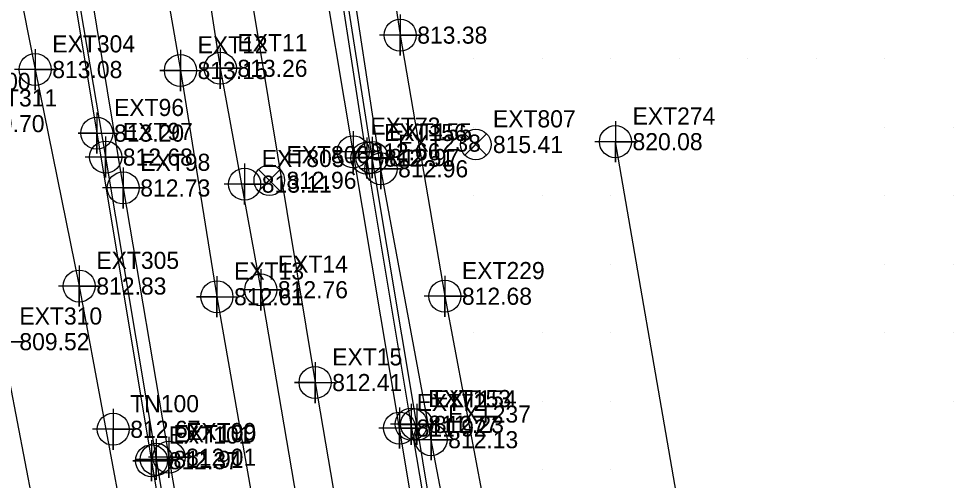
# Model space of a CAD drawing. Extents: x 1762120 to 1766775, y 709485 to 712965.
# Drawn here: x 1763773.6 to 1763910, y 712748.4 to 712815.9 of the extents above; entities that cross this region are included whole.
import ezdxf

# ---------------------------------------------------------------- set-up
doc = ezdxf.new("R2010")
doc.units = 0
for name, color, linetype in [('Default Symbol CELL', 7, 'Continuous'), ('Default Symbol Cogo Elevation', 7, 'Continuous'), ('Default Symbol Cogo Number', 7, 'Continuous'), ('Exist Building', 7, 'Continuous'), ('Exist Building Cogo Elevation', 7, 'Continuous'), ('Exist Building Cogo Number', 7, 'Continuous'), ('Exist Building Cogo Point CELL', 7, 'Continuous'), ('Exist DTM Breakline', 7, 'Continuous'), ('Exist DTM Breakline Cogo Elevation', 7, 'Continuous'), ('Exist DTM Breakline Cogo Number', 7, 'Continuous'), ('Exist DTM Breakline Cogo Point CELL', 7, 'Continuous'), ('Exist DTM Crownline', 7, 'Continuous'), ('Exist DTM Crownline Cogo Elevation', 7, 'Continuous'), ('Exist DTM Crownline Cogo Number', 7, 'Continuous'), ('Exist DTM Crownline Cogo Point CELL', 7, 'Continuous'), ('Exist DTM Drainline', 7, 'Continuous'), ('Exist DTM Drainline Cogo Elevation', 7, 'Continuous'), ('Exist DTM Drainline Cogo Number', 7, 'Continuous'), ('Exist DTM Drainline Cogo Point CELL', 7, 'Continuous'), ('Exist DTM QL2 LIDAR Elevation Point', 7, 'Continuous'), ('Exist Other Culture Fence Line Cogo Number', 7, 'Continuous'), ('Exist Roads Curbs', 7, 'Continuous'), ('Exist Roads Curbs Cogo Elevation', 7, 'Continuous'), ('Exist Roads Curbs Cogo Number', 7, 'Continuous'), ('Exist Roads Curbs Cogo Point CELL', 7, 'Continuous'), ('Exist Roads EOP', 7, 'Continuous'), ('Exist Roads EOP Cogo Elevation', 7, 'Continuous'), ('Exist Roads EOP Cogo Number', 7, 'Continuous'), ('Exist Roads EOP Cogo Point CELL', 7, 'Continuous'), ('Exist Roads EOP Other', 7, 'Continuous'), ('Exist Roads EOP Other Cogo Elevation', 7, 'Continuous'), ('Exist Roads EOP Other Cogo Number', 7, 'Continuous'), ('Exist Roads EOP Other Cogo Point CELL', 7, 'Continuous'), ('Exist Roads EOT', 7, 'Continuous'), ('Exist Roads EOT Cogo Elevation', 7, 'Continuous'), ('Exist Roads EOT Cogo Number', 7, 'Continuous'), ('Exist Roads EOT Cogo Point CELL', 7, 'Continuous'), ('Exist Utilities Water UG Line SUE LOS C Cogo Elevation', 7, 'Continuous'), ('Exist Utilities Water UG Line SUE LOS C Cogo Number', 7, 'Continuous'), ('Exist Utilities Water UG Line SUE LOS C Cogo Point CELL', 7, 'Continuous'), ('Exist Utilities Water Valve CELL', 7, 'Continuous'), ('Exist Utilities Water Valve Cogo Elevation', 7, 'Continuous'), ('Exist Utilities Water Valve Cogo Number', 7, 'Continuous')]:
    doc.layers.add(name, color=color, linetype=linetype)

msp = doc.modelspace()

# ---------------------------------------------------------------- linework, layer by layer
at = {"layer": 'Default Symbol CELL'}
msp.add_lwpolyline([(1763787.39, 712758.89), (1763787.39, 712752.89), (1763787.39, 712755.89), (1763790.39, 712755.89), (1763784.39, 712755.89)], dxfattribs=at)
msp.add_circle((1763787.39, 712755.89), 2.34, dxfattribs=at)
at = {"layer": 'Exist Building'}
msp.add_line((1763873.08, 712726.35), (1763860.69, 712797.91), dxfattribs=at)
at = {"layer": 'Exist Building Cogo Point CELL'}
msp.add_lwpolyline([(1763860.69, 712800.91), (1763860.69, 712794.91), (1763860.69, 712797.91), (1763863.69, 712797.91), (1763857.69, 712797.91)], dxfattribs=at)
msp.add_circle((1763860.69, 712797.91), 2.34, dxfattribs=at)
at = {"layer": 'Exist DTM Breakline'}
msp.add_lwpolyline([(1763768.87, 712844.44), (1763776.01, 712808.45), (1763782.44, 712776.82), (1763789.54, 712738.64), (1763792.6, 712718.34), (1763784.29, 712719.01), (1763777.9, 712733.6), (1763771.21, 712768.69), (1763764.65, 712800.55), (1763763.2, 712827.98)], dxfattribs=at)
at = {"layer": 'Exist DTM Breakline Cogo Point CELL'}
for points in [[(1763776.01, 712811.45), (1763776.01, 712805.45), (1763776.01, 712808.45), (1763779.01, 712808.45), (1763773.01, 712808.45)], [(1763782.44, 712779.82), (1763782.44, 712773.82), (1763782.44, 712776.82), (1763785.44, 712776.82), (1763779.44, 712776.82)], [(1763771.21, 712771.69), (1763771.21, 712765.69), (1763771.21, 712768.69), (1763774.21, 712768.69), (1763768.21, 712768.69)]]:
    msp.add_lwpolyline(points, dxfattribs=at)
for centre in [(1763776.01, 712808.45), (1763782.44, 712776.82)]:
    msp.add_circle(centre, 2.34, dxfattribs=at)
at = {"layer": 'Exist DTM Crownline'}
msp.add_lwpolyline([(1763783.92, 712926.06), (1763790.26, 712887.32), (1763795.18, 712859.53), (1763803.03, 712808.63), (1763808.93, 712776.27), (1763814.52, 712743.37), (1763820.27, 712708.85), (1763825.75, 712675.92), (1763832.22, 712637.52), (1763836.73, 712610.54), (1763843.63, 712568.93)], dxfattribs=at)
at = {"layer": 'Exist DTM Crownline Cogo Point CELL'}
for points in [[(1763803.03, 712811.63), (1763803.03, 712805.63), (1763803.03, 712808.63), (1763806.03, 712808.63), (1763800.03, 712808.63)], [(1763808.93, 712779.27), (1763808.93, 712773.27), (1763808.93, 712776.27), (1763811.93, 712776.27), (1763805.93, 712776.27)]]:
    msp.add_lwpolyline(points, dxfattribs=at)
for centre in [(1763803.03, 712808.63), (1763808.93, 712776.27)]:
    msp.add_circle(centre, 2.34, dxfattribs=at)
at = {"layer": 'Exist DTM Drainline'}
for points in [[(1763888.18, 712675.96), (1763883.47, 712673.43), (1763879.42, 712672.24), (1763861.29, 712669.22), (1763855.83, 712669.14), (1763849.99, 712671.4), (1763845.81, 712675.27), (1763843.64, 712680.2), (1763837.25, 712719.08), (1763830.88, 712756.63), (1763824.42, 712795.51), (1763818.53, 712833.61)], [(1763781.29, 712825.28), (1763786.3, 712795.66), (1763793.69, 712751.5), (1763799.33, 712717.75), (1763805.44, 712681.56), (1763811.95, 712643.04), (1763816.53, 712615.56)]]:
    msp.add_lwpolyline(points, dxfattribs=at)
at = {"layer": 'Exist DTM Drainline Cogo Point CELL'}
for points in [[(1763786.3, 712798.66), (1763786.3, 712792.66), (1763786.3, 712795.66), (1763789.3, 712795.66), (1763783.3, 712795.66)], [(1763824.42, 712798.51), (1763824.42, 712792.51), (1763824.42, 712795.51), (1763827.42, 712795.51), (1763821.42, 712795.51)], [(1763830.88, 712759.63), (1763830.88, 712753.63), (1763830.88, 712756.63), (1763833.88, 712756.63), (1763827.88, 712756.63)], [(1763793.69, 712754.5), (1763793.69, 712748.5), (1763793.69, 712751.5), (1763796.69, 712751.5), (1763790.69, 712751.5)]]:
    msp.add_lwpolyline(points, dxfattribs=at)
for centre in [(1763786.3, 712795.66), (1763824.42, 712795.51), (1763830.88, 712756.63), (1763793.69, 712751.5)]:
    msp.add_circle(centre, 2.34, dxfattribs=at)
at = {"layer": 'Exist DTM QL2 LIDAR Elevation Point'}
for p, q in [((1763840, 712810), (1763840, 712810)), ((1763850, 712810), (1763850, 712810)), ((1763860, 712810), (1763860, 712810)), ((1763870, 712810), (1763870, 712810)), ((1763880, 712810), (1763880, 712810)), ((1763890, 712810), (1763890, 712810)), ((1763900, 712810), (1763900, 712810)), ((1763840, 712800), (1763840, 712800)), ((1763850, 712800), (1763850, 712800)), ((1763900, 712800), (1763900, 712800)), ((1763910, 712800), (1763910, 712800)), ((1763840, 712790), (1763840, 712790)), ((1763850, 712790), (1763850, 712790)), ((1763860, 712790), (1763860, 712790)), ((1763900, 712790), (1763900, 712790)), ((1763910, 712790), (1763910, 712790)), ((1763840, 712780), (1763840, 712780)), ((1763850, 712780), (1763850, 712780)), ((1763860, 712780), (1763860, 712780)), ((1763900, 712780), (1763900, 712780)), ((1763910, 712780), (1763910, 712780)), ((1763840, 712770), (1763840, 712770)), ((1763850, 712770), (1763850, 712770)), ((1763860, 712770), (1763860, 712770)), ((1763900, 712770), (1763900, 712770)), ((1763910, 712770), (1763910, 712770)), ((1763850, 712760), (1763850, 712760)), ((1763860, 712760), (1763860, 712760)), ((1763910, 712760), (1763910, 712760)), ((1763850, 712750), (1763850, 712750)), ((1763860, 712750), (1763860, 712750))]:
    msp.add_line(p, q, dxfattribs=at)
at = {"layer": 'Exist Roads Curbs'}
for points in [[(1763764.47, 712921.99), (1763771.22, 712881.37), (1763777.8, 712842.52), (1763785.02, 712799.16), (1763793, 712751.3), (1763798.52, 712717.85), (1763798.75, 712716.41), (1763801.86, 712697.92), (1763802.15, 712696.94), (1763804.69, 712681.5), (1763811.15, 712642.97), (1763816.5, 712611.82), (1763823.37, 712570.12)], [(1763887.91, 712676.61), (1763883.1, 712673.99), (1763879.53, 712672.95), (1763861.13, 712669.8), (1763855.72, 712669.96), (1763851.55, 712671.35), (1763848.14, 712673.75), (1763845.52, 712677.19), (1763844.34, 712680.6), (1763837.88, 712719.14), (1763831.69, 712756.6), (1763825.17, 712795.6), (1763818.68, 712837.18), (1763818.59, 712840.74), (1763820.69, 712846.56), (1763822.71, 712849.77), (1763826.55, 712853.15), (1763830.57, 712855.11), (1763844.34, 712857.64), (1763850.13, 712857.27), (1763855.59, 712854.56), (1763859.32, 712849.84), (1763861.63, 712843.38)]]:
    msp.add_lwpolyline(points, dxfattribs=at)
at = {"layer": 'Exist Roads Curbs Cogo Point CELL'}
for points in [[(1763785.02, 712802.16), (1763785.02, 712796.16), (1763785.02, 712799.16), (1763782.29, 712799.16), (1763788.02, 712799.16)], [(1763825.17, 712798.6), (1763825.17, 712792.6), (1763825.17, 712795.6), (1763822.44, 712795.6), (1763828.17, 712795.6)], [(1763831.69, 712759.6), (1763831.69, 712753.6), (1763831.69, 712756.6), (1763828.96, 712756.6), (1763834.69, 712756.6)], [(1763793, 712754.3), (1763793, 712748.3), (1763793, 712751.3), (1763790.27, 712751.3), (1763796, 712751.3)]]:
    msp.add_lwpolyline(points, dxfattribs=at)
for centre in [(1763785.02, 712799.16), (1763825.17, 712795.6), (1763831.69, 712756.6), (1763793, 712751.3)]:
    msp.add_circle(centre, 2.34, dxfattribs=at)
at = {"layer": 'Exist Roads EOP'}
for points in [[(1763767.08, 712922.22), (1763773.82, 712881.97), (1763780.33, 712842.9), (1763788.85, 712791.15), (1763795.54, 712751.81), (1763801.2, 712718.14), (1763807.39, 712682.01), (1763813.81, 712643.39), (1763818.94, 712612.35), (1763825.97, 712570.73)], [(1763872.94, 712669.26), (1763861.77, 712667.4), (1763856.13, 712667.2), (1763850.39, 712669.07), (1763848.28, 712670.39), (1763843.44, 712675.41), (1763841.77, 712679.86), (1763835.93, 712715.54), (1763829.18, 712756.07), (1763822.43, 712796.44), (1763817.32, 712826.97), (1763816.07, 712838.81), (1763818.95, 712848.93), (1763823.98, 712854.42), (1763830.82, 712857.79), (1763839.26, 712859.24)]]:
    msp.add_lwpolyline(points, dxfattribs=at)
at = {"layer": 'Exist Roads EOP Cogo Point CELL'}
for points in [[(1763822.43, 712799.44), (1763822.43, 712793.44), (1763822.43, 712796.44), (1763825.43, 712796.44), (1763819.43, 712796.44)], [(1763788.85, 712794.15), (1763788.85, 712788.15), (1763788.85, 712791.15), (1763791.85, 712791.15), (1763785.85, 712791.15)], [(1763829.18, 712759.07), (1763829.18, 712753.07), (1763829.18, 712756.07), (1763832.18, 712756.07), (1763826.18, 712756.07)], [(1763795.54, 712754.81), (1763795.54, 712748.81), (1763795.54, 712751.81), (1763798.54, 712751.81), (1763792.54, 712751.81)]]:
    msp.add_lwpolyline(points, dxfattribs=at)
for centre in [(1763822.43, 712796.44), (1763788.85, 712791.15), (1763829.18, 712756.07), (1763795.54, 712751.81)]:
    msp.add_circle(centre, 2.34, dxfattribs=at)
at = {"layer": 'Exist Roads EOP Other'}
for points in [[(1763823.74, 712850.66), (1763829.27, 712813.48), (1763835.79, 712775.33), (1763842.87, 712737.85), (1763850.06, 712700.09), (1763853.73, 712680.41), (1763855.6, 712670.27)], [(1763848.82, 712673.42), (1763847.82, 712679.98), (1763840.4, 712719.75), (1763833.78, 712754.37), (1763826.48, 712793.95), (1763821.46, 712826.92), (1763819.12, 712842.2)]]:
    msp.add_lwpolyline(points, dxfattribs=at)
at = {"layer": 'Exist Roads EOP Other Cogo Point CELL'}
for points in [[(1763829.27, 712816.48), (1763829.27, 712810.48), (1763829.27, 712813.48), (1763832.27, 712813.48), (1763826.27, 712813.48)], [(1763826.48, 712796.95), (1763826.48, 712790.95), (1763826.48, 712793.95), (1763829.48, 712793.95), (1763823.48, 712793.95)], [(1763835.79, 712778.33), (1763835.79, 712772.33), (1763835.79, 712775.33), (1763838.79, 712775.33), (1763832.79, 712775.33)], [(1763833.78, 712757.37), (1763833.78, 712751.37), (1763833.78, 712754.37), (1763836.78, 712754.37), (1763830.78, 712754.37)]]:
    msp.add_lwpolyline(points, dxfattribs=at)
for centre in [(1763829.27, 712813.48), (1763826.48, 712793.95), (1763835.79, 712775.33), (1763833.78, 712754.37)]:
    msp.add_circle(centre, 2.34, dxfattribs=at)
at = {"layer": 'Exist Roads EOT'}
for points in [[(1763789.83, 712926.88), (1763795.99, 712888.05), (1763800.75, 712859.94), (1763807.25, 712820.95), (1763816.86, 712762.72), (1763822.15, 712731.85), (1763825.7, 712709.77), (1763831.21, 712676.82), (1763837.74, 712638.56), (1763842.2, 712611.18), (1763849.14, 712569.76)], [(1763777.49, 712924.55), (1763781.49, 712903.2), (1763789.16, 712854.7), (1763797.21, 712808.31), (1763802.54, 712775.26), (1763808.3, 712742.17), (1763814.09, 712707.89), (1763819.56, 712674.99), (1763826.1, 712636.38), (1763830.49, 712609.67), (1763837.44, 712567.81)]]:
    msp.add_lwpolyline(points, dxfattribs=at)
at = {"layer": 'Exist Roads EOT Cogo Point CELL'}
for points in [[(1763797.21, 712811.31), (1763797.21, 712805.31), (1763797.21, 712808.31), (1763794.21, 712808.31), (1763800.21, 712808.31)], [(1763802.54, 712778.26), (1763802.54, 712772.26), (1763802.54, 712775.26), (1763799.54, 712775.26), (1763805.54, 712775.26)], [(1763816.86, 712765.72), (1763816.86, 712759.72), (1763816.86, 712762.72), (1763813.86, 712762.72), (1763819.86, 712762.72)]]:
    msp.add_lwpolyline(points, dxfattribs=at)
for centre in [(1763797.21, 712808.31), (1763802.54, 712775.26), (1763816.86, 712762.72)]:
    msp.add_circle(centre, 2.34, dxfattribs=at)
at = {"layer": 'Exist Utilities Water UG Line SUE LOS C Cogo Point CELL'}
msp.add_lwpolyline([(1763806.58, 712794.71), (1763806.58, 712788.71), (1763806.58, 712791.71), (1763809.58, 712791.71), (1763803.58, 712791.71)], dxfattribs=at)
msp.add_circle((1763806.58, 712791.71), 2.34, dxfattribs=at)
at = {"layer": 'Exist Utilities Water Valve CELL'}
for points in [[(1763841.88, 712799.07), (1763838.73, 712795.92), (1763840.31, 712797.5), (1763841.88, 712795.92), (1763838.73, 712799.07)], [(1763811.75, 712793.84), (1763808.6, 712790.69), (1763810.18, 712792.27), (1763811.75, 712790.69), (1763808.6, 712793.84)]]:
    msp.add_lwpolyline(points, dxfattribs=at)
for centre in [(1763840.31, 712797.5), (1763810.18, 712792.27)]:
    msp.add_circle(centre, 2.23, dxfattribs=at)

# ---------------------------------------------------------------- texts
at = {"layer": 'Default Symbol Cogo Elevation'}
msp.add_text('812.67', height=2.5, dxfattribs=at).set_placement((1763789.89, 712754.64))
at = {"layer": 'Default Symbol Cogo Number'}
msp.add_text('TN100', height=2.5, dxfattribs=at).set_placement((1763789.89, 712758.39))
at = {"layer": 'Exist Building Cogo Elevation'}
msp.add_text('820.08', height=2.5, dxfattribs=at).set_placement((1763863.19, 712796.66))
at = {"layer": 'Exist Building Cogo Number'}
msp.add_text('EXT274', height=2.5, dxfattribs=at).set_placement((1763863.19, 712800.41))
at = {"layer": 'Exist DTM Breakline Cogo Elevation'}
for s, p in [('813.08', (1763778.51, 712807.2)), ('809.70', (1763767.15, 712799.3)), ('812.83', (1763784.94, 712775.57)), ('809.52', (1763773.71, 712767.44))]:
    msp.add_text(s, height=2.5, dxfattribs=at).set_placement(p)
at = {"layer": 'Exist DTM Breakline Cogo Number'}
for s, p in [('EXT304', (1763778.51, 712810.95)), ('EXT311', (1763767.15, 712803.05)), ('EXT305', (1763784.94, 712779.32)), ('EXT310', (1763773.71, 712771.19))]:
    msp.add_text(s, height=2.5, dxfattribs=at).set_placement(p)
at = {"layer": 'Exist DTM Crownline Cogo Elevation'}
for s, p in [('813.26', (1763805.53, 712807.38)), ('812.76', (1763811.43, 712775.03))]:
    msp.add_text(s, height=2.5, dxfattribs=at).set_placement(p)
at = {"layer": 'Exist DTM Crownline Cogo Number'}
for s, p in [('EXT11', (1763805.53, 712811.13)), ('EXT14', (1763811.43, 712778.78))]:
    msp.add_text(s, height=2.5, dxfattribs=at).set_placement(p)
at = {"layer": 'Exist DTM Drainline Cogo Elevation'}
for s, p in [('812.68', (1763788.8, 712794.41)), ('812.51', (1763826.92, 712794.26)), ('811.77', (1763833.38, 712755.38)), ('811.91', (1763796.19, 712750.25))]:
    msp.add_text(s, height=2.5, dxfattribs=at).set_placement(p)
at = {"layer": 'Exist DTM Drainline Cogo Number'}
for s, p in [('EXT97', (1763788.8, 712798.16)), ('EXT156', (1763826.92, 712798.01)), ('EXT153', (1763833.38, 712759.13)), ('EXT100', (1763796.19, 712754))]:
    msp.add_text(s, height=2.5, dxfattribs=at).set_placement(p)
at = {"layer": 'Exist Other Culture Fence Line Cogo Number'}
msp.add_text('EXT300', height=2.5, dxfattribs=at).set_placement((1763763.27, 712805.47))
at = {"layer": 'Exist Roads Curbs Cogo Elevation'}
for s, p in [('813.20', (1763787.52, 712797.91)), ('812.97', (1763827.67, 712794.35)), ('812.23', (1763834.19, 712755.35)), ('812.37', (1763795.5, 712750.05))]:
    msp.add_text(s, height=2.5, dxfattribs=at).set_placement(p)
at = {"layer": 'Exist Roads Curbs Cogo Number'}
for s, p in [('EXT96', (1763787.52, 712801.66)), ('EXT155', (1763827.67, 712798.1)), ('EXT154', (1763834.19, 712759.1)), ('EXT101', (1763795.5, 712753.8))]:
    msp.add_text(s, height=2.5, dxfattribs=at).set_placement(p)
at = {"layer": 'Exist Roads EOP Cogo Elevation'}
for s, p in [('812.66', (1763824.93, 712795.19)), ('812.73', (1763791.35, 712789.9)), ('811.92', (1763831.68, 712754.82)), ('812.01', (1763798.04, 712750.56))]:
    msp.add_text(s, height=2.5, dxfattribs=at).set_placement(p)
at = {"layer": 'Exist Roads EOP Cogo Number'}
for s, p in [('EXT73', (1763824.93, 712798.94)), ('EXT98', (1763791.35, 712793.65)), ('EXT72', (1763831.68, 712758.57)), ('EXT99', (1763798.04, 712754.31))]:
    msp.add_text(s, height=2.5, dxfattribs=at).set_placement(p)
at = {"layer": 'Exist Roads EOP Other Cogo Elevation'}
for s, p in [('813.38', (1763831.77, 712812.23)), ('812.96', (1763828.98, 712792.7)), ('812.68', (1763838.29, 712774.08)), ('812.13', (1763836.28, 712753.12))]:
    msp.add_text(s, height=2.5, dxfattribs=at).set_placement(p)
at = {"layer": 'Exist Roads EOP Other Cogo Number'}
for s, p in [('EXT238', (1763828.98, 712796.45)), ('EXT229', (1763838.29, 712777.83)), ('EXT237', (1763836.28, 712756.87))]:
    msp.add_text(s, height=2.5, dxfattribs=at).set_placement(p)
at = {"layer": 'Exist Roads EOT Cogo Elevation'}
for s, p in [('813.15', (1763799.71, 712807.06)), ('812.61', (1763805.04, 712774.01)), ('812.41', (1763819.36, 712761.47))]:
    msp.add_text(s, height=2.5, dxfattribs=at).set_placement(p)
at = {"layer": 'Exist Roads EOT Cogo Number'}
for s, p in [('EXT12', (1763799.71, 712810.81)), ('EXT13', (1763805.04, 712777.76)), ('EXT15', (1763819.36, 712765.22))]:
    msp.add_text(s, height=2.5, dxfattribs=at).set_placement(p)
at = {"layer": 'Exist Utilities Water UG Line SUE LOS C Cogo Elevation'}
msp.add_text('813.11', height=2.5, dxfattribs=at).set_placement((1763809.08, 712790.46))
at = {"layer": 'Exist Utilities Water UG Line SUE LOS C Cogo Number'}
msp.add_text('EXT805', height=2.5, dxfattribs=at).set_placement((1763809.08, 712794.21))
at = {"layer": 'Exist Utilities Water Valve Cogo Elevation'}
for s, p in [('815.41', (1763842.81, 712796.25)), ('812.96', (1763812.68, 712791.02))]:
    msp.add_text(s, height=2.5, dxfattribs=at).set_placement(p)
at = {"layer": 'Exist Utilities Water Valve Cogo Number'}
for s, p in [('EXT807', (1763842.81, 712800)), ('EXT806', (1763812.68, 712794.77))]:
    msp.add_text(s, height=2.5, dxfattribs=at).set_placement(p)

doc.saveas('drawing.dxf')
